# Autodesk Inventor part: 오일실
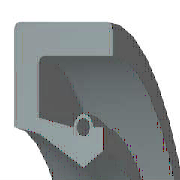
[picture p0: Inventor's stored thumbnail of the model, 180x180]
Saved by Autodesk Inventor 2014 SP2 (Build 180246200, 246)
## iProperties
IsCustomPart: 1
Company: 한국ATC센터
Created: 2014-11
Part Number: 오일실
Material: 고무
Description: 오일-실
Document SubType Name: Modeling
Standard: KS B 2804
Designer: KYOUNG IL JANG
Standards Organization: KS
Language: ko-KR
Size Designation: S - 25 40 8
Categories: <MemberInstance><Categories><Category DisplayName="샤프트 부품" InternalName="7f7aeb1f-a693-4053-b835-cee3144e0d98" Mnemonic="SHFT"><Category DisplayName="실링" Intern
Density: 0.93 g/cm^3
Mass: 2.48215 g
Surface Area: 40.3381 cm^2
Volume: 2.66898 cm^3
Appearance: 고무 - 검은색 - 버전 1.1
Author: KYOUNG IL JANG
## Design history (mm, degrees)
revolve "본체" stored, may be unused: angle "d17" = 90 deg
revolve "스프링1" stored, may be unused: angle "d18" = 90 deg
body "Solid1"
sketch "스케치1"
  geometry: L1 (0, 20)-(8, 20); L2 (8, 20)-(8, 18.75); L3 (8, 18.75)-(1.75, 18.75); L4 (0, 20)-(0, 14.6); L5 (0, 14.6)-(1.75, 14.25); L6 (1.75, 14.25)-(4.9, 12.5); L7 (4.9, 12.5)-(0, 12.5); L8 (6.3, 13.375)-(6.3, 14.6); L9 (0, 0)-(9.586, 0) reference; L10 (4.9, 12.5)-(6.3, 13.375); L11 (0, 18)-(0, -3) reference; L12 (-1.917, 0)-(11.503, 0) reference; L13 (4.2, 14.6)-(1.75, 15.09); L14 (1.75, 15.09)-(1.75, 18.75); L15 (6.3, 14.6)-(5.6, 14.6); C1 r 0.455 at (4.9, 14.6); A1 r 0.7 centre (4.9, 14.6) between (5.6, 14.6) and (4.2, 14.6)
  constraints: 26 end point, 5 horizontal alignment, 4 perpendicular, 2 centre point, 2 collinear, 2 horizontal, 2 parallel, 2 point on circle, 2 point on line, 2 vertical alignment, 1 coincident
  dimensions: "d0" = 40 diameter of L1 L9 (= SD2); "d1" = 26.75 diameter of L8.start L9 (= ABDM); "d2" = 1.25 distance of L1.end L2.end (computed from SD); "d3" = 0.91 diameter of C1 (= SPDI); "d4" = 1.4 diameter of A1 (= SPDA); "d5" = 25 diameter of L6.end L9 (= NND); "d6" = 28.5 diameter of L5.end L9 (= TKDM); "d7" = 29.2 diameter of L4.end L9 (= HLDM); "d8" = 4.9 distance from line of C1.centre L4 (= SPDST); "d9" = 6.3 distance between parallel lines of L8 L4 (= SDI); "d10" = 8 distance between parallel lines of L2 L4 (= SWDT); "d12" = 1.75 distance between parallel lines of L14 L4 (= SD)
fillet "모깎기1" dims "d11" = 0.3 (= RR)
other parameters: "SD2" = 40 [user parameter; used in 1 equation term], "SWDT" = 8 [user parameter; used in 1 equation term], "RR" = 0.3 [user parameter; used in 1 equation term], "SD" = 1.75 [user parameter; used in 2 equation terms], "NND" = 25 [user parameter; used in 1 equation term], "SPDA" = 1.4 [user parameter; used in 1 equation term], "SPDI" = 0.91 [user parameter; used in 1 equation term], "TKDM" = 28.5 [user parameter; used in 1 equation term], "HLDM" = 29.2 [user parameter; used in 1 equation term], "ABDM" = 26.75 [user parameter; used in 1 equation term], "SDI" = 6.3 [user parameter; used in 1 equation term], "SPDST" = 4.9 [user parameter; used in 1 equation term], "d13" = 0, "d14" = 0, "d15" = 0, "LAB" = 0.35 [user parameter]
